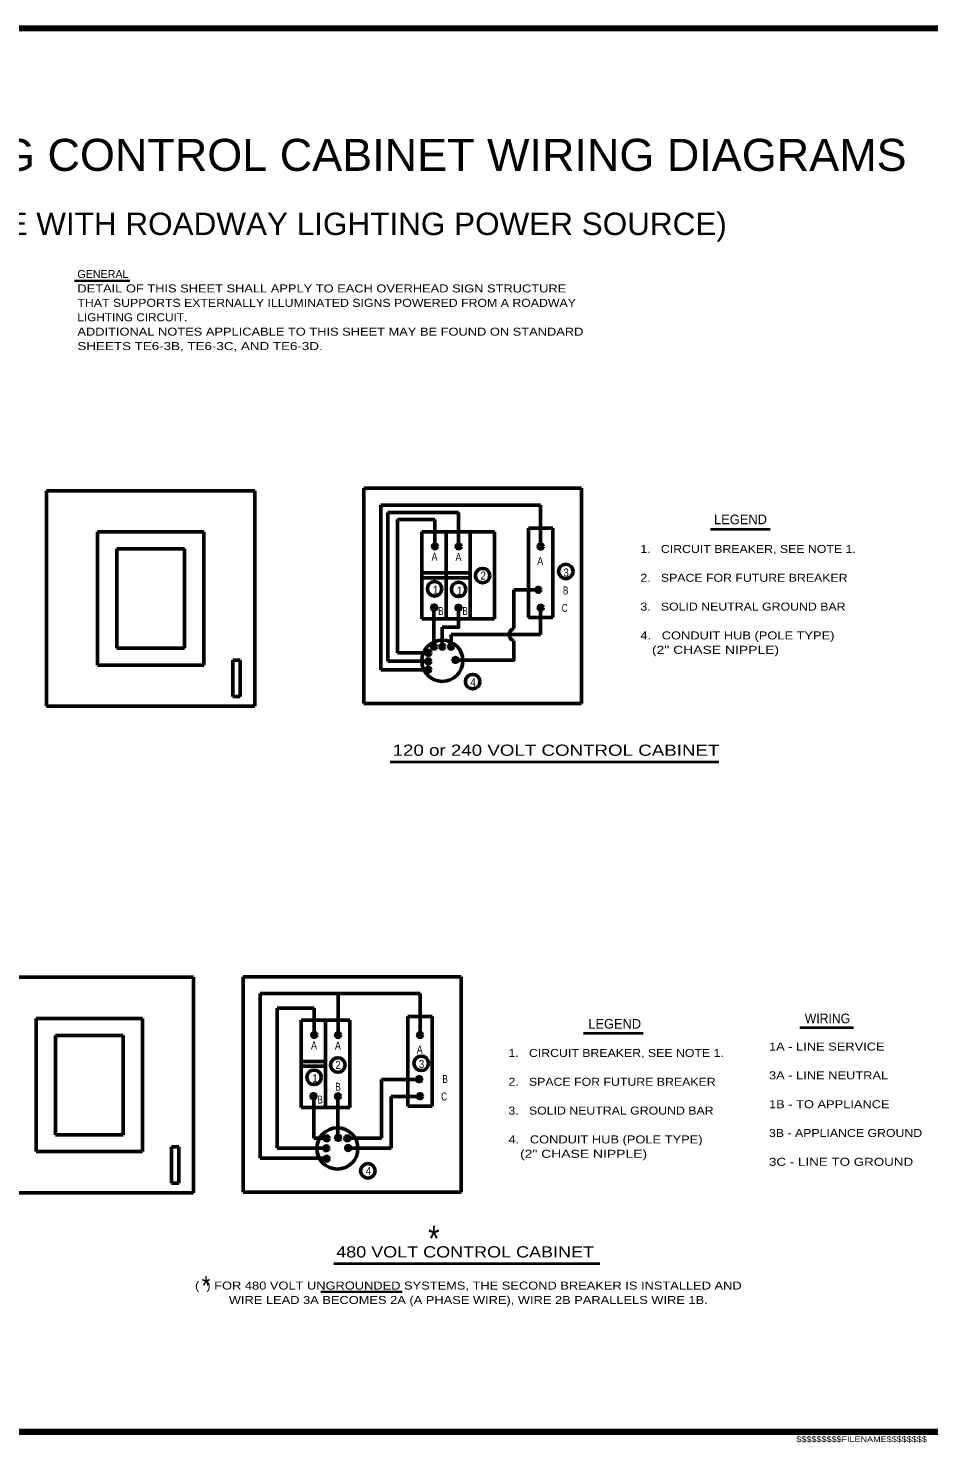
# Model space of a CAD drawing. Extents: x -38 to 818, y -13 to 531.
# Drawn here: x 250 to 588, y -6 to 524 of the extents above; entities that cross this region are included whole.
import ezdxf
from ezdxf.enums import TextEntityAlignment as Align

# ---------------------------------------------------------------- set-up
doc = ezdxf.new("R2010")
doc.units = 0
doc.header["$LTSCALE"] = 1.2
doc.layers.add('1', color=7, linetype='Continuous', lineweight=53)

msp = doc.modelspace()

# ---------------------------------------------------------------- hatches: boundary and pattern name
at = {"layer": '1'}
for points in [[(403.606, 330.209, 1), (401.791, 330.209, 1)], [(412.484, 330.191, 1), (410.669, 330.191, 1)], [(443.214, 330.181, 1), (441.399, 330.181, 1)], [(442.359, 313.935, 1), (440.544, 313.935, 1)], [(403.298, 307.273, 1), (401.483, 307.273, 1)], [(412.44, 307.195, 1), (410.625, 307.195, 1)], [(443.228, 307.234, 1), (441.413, 307.234, 1)], [(403.253, 292.596, 1), (401.438, 292.596, 1)], [(406.36, 292.596, 1), (404.545, 292.596, 1)], [(409.66, 292.596, 1), (407.845, 292.596, 1)], [(401.109, 290.282, 1), (399.294, 290.282, 1)], [(401.133, 287.126, 1), (399.318, 287.126, 1)], [(411.322, 287.656, 1), (409.507, 287.656, 1)], [(401.109, 283.994, 1), (399.294, 283.994, 1)], [(358.418, 147.099, 1), (356.603, 147.099, 1)], [(367.296, 147.081, 1), (365.481, 147.081, 1)], [(398.026, 147.072, 1), (396.211, 147.072, 1)], [(397.682, 130.519, 1), (395.867, 130.519, 1)], [(358.111, 124.163, 1), (356.296, 124.163, 1)], [(367.253, 124.085, 1), (365.438, 124.085, 1)], [(398.04, 124.124, 1), (396.225, 124.124, 1)], [(363.019, 108.354, 1), (361.204, 108.354, 1)], [(367.338, 108.551, 1), (365.523, 108.551, 1)], [(370.773, 108.354, 1), (368.958, 108.354, 1)], [(362.92, 104.623, 1), (361.105, 104.623, 1)], [(363.019, 100.695, 1), (361.204, 100.695, 1)], [(371.068, 104.721, 1), (369.253, 104.721, 1)]]:
    msp.add_hatch(color=256, dxfattribs=at).paths.add_polyline_path(points)

# ---------------------------------------------------------------- linework, layer by layer
at = {"layer": '1', "lineweight": 35}
for p, q in [((267.611, 429.766), (288.324, 429.766)), ((359.986, 50.809), (390.466, 50.809))]:
    msp.add_line(p, q, dxfattribs=at)
at = {"layer": '1'}
for p, q in [((257.116, 351.08), (257.116, 270.312)), ((257.116, 351.08), (335.161, 351.08)), ((335.161, 351.08), (335.161, 270.312)), ((376.022, 352.025), (376.022, 271.257)), ((376.022, 352.025), (457.697, 352.025)), ((457.697, 352.025), (457.697, 271.257)), ((382.375, 345.672), (382.375, 283.962)), ((382.375, 345.672), (442.309, 345.672)), ((442.309, 345.672), (442.309, 329.337)), ((385.097, 342.95), (385.097, 287.154)), ((385.097, 342.95), (411.559, 342.95)), ((388.727, 340.227), (388.727, 290.315)), ((388.727, 340.227), (402.66, 340.227)), ((402.66, 340.227), (402.66, 329.337)), ((411.559, 342.95), (411.559, 329.337)), ((276.173, 335.652), (276.173, 285.74)), ((276.173, 335.652), (316.103, 335.652)), ((316.103, 335.652), (316.103, 285.74)), ((397.802, 335.69), (397.802, 303.02)), ((397.802, 335.69), (425.027, 335.69)), ((406.877, 335.69), (406.877, 303.02)), ((415.952, 335.69), (415.952, 303.02)), ((425.027, 335.69), (425.027, 303.02)), ((437.772, 303.501), (437.772, 337.078)), ((437.772, 337.078), (446.847, 337.078)), ((446.847, 303.501), (446.847, 337.078)), ((283.434, 329.3), (283.434, 292.092)), ((283.434, 329.3), (308.844, 329.3)), ((308.844, 329.3), (308.844, 292.092)), ((397.802, 320.262), (415.952, 320.262)), ((415.952, 318.447), (397.802, 318.447)), ((432.287, 299.39), (432.287, 313.91)), ((432.287, 313.91), (442.309, 313.91)), ((402.334, 308.038), (402.334, 291.703)), ((442.309, 297.148), (442.309, 308.038)), ((425.027, 303.02), (397.802, 303.02)), ((437.772, 303.501), (446.847, 303.501)), ((405.453, 299.871), (405.453, 291.703)), ((408.732, 297.148), (442.309, 297.148)), ((408.732, 297.148), (408.732, 291.703)), ((283.434, 292.092), (308.844, 292.092)), ((326.994, 287.555), (326.994, 273.942)), ((326.994, 287.555), (329.716, 287.555)), ((329.716, 287.555), (329.716, 273.942)), ((385.097, 287.154), (401.095, 287.154)), ((388.727, 290.315), (401.095, 290.315)), ((276.173, 285.74), (316.103, 285.74)), ((382.375, 283.962), (401.095, 283.962)), ((326.994, 273.942), (329.716, 273.942)), ((376.022, 271.257), (457.697, 271.257)), ((257.116, 270.312), (335.161, 270.312)), ((234.134, 168.699), (312.179, 168.699)), ((312.179, 168.699), (312.179, 87.931)), ((330.835, 168.915), (330.835, 88.147)), ((330.835, 168.915), (412.51, 168.915)), ((412.51, 168.915), (412.51, 88.147)), ((337.187, 162.562), (337.187, 100.852)), ((337.187, 162.562), (397.122, 162.562)), ((366.372, 162.562), (366.372, 146.227)), ((397.122, 162.562), (397.122, 146.227)), ((343.54, 157.117), (343.54, 104.653)), ((343.54, 157.117), (357.473, 157.117)), ((357.473, 157.117), (357.473, 146.227)), ((392.585, 120.391), (392.585, 153.968)), ((392.585, 153.968), (401.66, 153.968)), ((401.66, 120.391), (401.66, 153.968)), ((253.191, 153.271), (253.191, 103.359)), ((253.191, 153.271), (293.121, 153.271)), ((293.121, 153.271), (293.121, 103.359)), ((352.615, 152.58), (352.615, 119.91)), ((352.615, 152.58), (370.765, 152.58)), ((361.69, 152.58), (361.69, 119.91)), ((370.765, 152.58), (370.765, 119.91)), ((260.451, 146.919), (260.451, 109.711)), ((260.451, 146.919), (285.861, 146.919)), ((285.861, 146.919), (285.861, 109.711)), ((352.615, 137.152), (361.69, 137.152)), ((361.69, 135.337), (352.615, 135.337)), ((396.771, 130.343), (382.637, 130.343)), ((382.637, 108.447), (382.637, 130.343)), ((357.312, 124.059), (357.312, 108.447)), ((366.342, 123.961), (366.342, 108.463)), ((397.262, 124.059), (386.267, 124.059)), ((386.267, 104.653), (386.267, 124.059)), ((370.765, 119.91), (352.615, 119.91)), ((392.585, 120.391), (401.66, 120.391)), ((260.451, 109.711), (285.861, 109.711)), ((357.312, 108.447), (361.631, 108.447)), ((369.974, 108.447), (382.637, 108.447)), ((253.191, 103.359), (293.121, 103.359)), ((304.011, 105.174), (304.011, 91.561)), ((304.011, 105.174), (306.734, 105.174)), ((306.734, 105.174), (306.734, 91.561)), ((337.187, 100.852), (361.631, 100.852)), ((343.54, 104.653), (361.631, 104.653)), ((369.974, 104.653), (386.267, 104.653)), ((304.011, 91.561), (306.734, 91.561)), ((234.134, 87.931), (312.179, 87.931)), ((330.835, 88.147), (412.51, 88.147))]:
    msp.add_line(p, q, dxfattribs=at)
at = {"layer": '1', "lineweight": 40}
for p, q in [((505.993, 336.634), (528.324, 336.634)), ((385.936, 249.442), (509.163, 249.442)), ((539.447, 149.877), (559.574, 149.877)), ((458.415, 147.739), (480.746, 147.739)), ((364.808, 61.42), (464.568, 61.42))]:
    msp.add_line(p, q, dxfattribs=at)
at = {"layer": '1', "lineweight": 158}
msp.add_line((811.159, -1.718), (19.559, -1.718), dxfattribs=at)
msp.add_lwpolyline([(811.159, 524.382), (19.459, 524.282), (19.559, -1.718)], dxfattribs=at)
at = {"layer": '1'}
for points in [[(405.453, 299.871), (411.572, 299.871), (411.572, 308.038)], [(409.6, 287.592), (432.287, 287.592), (432.287, 294.852)]]:
    msp.add_lwpolyline(points, dxfattribs=at)
for centre, radius in [((402.698, 330.209), 0.907), ((411.576, 330.191), 0.907), ((442.306, 330.181), 0.907), ((451.762, 320.804), 2.723), ((420.57, 319.244), 2.723), ((402.574, 314.323), 2.723), ((411.572, 314.083), 2.723), ((441.452, 313.935), 0.907), ((402.391, 307.273), 0.907), ((411.533, 307.195), 0.907), ((442.32, 307.234), 0.907), ((405.453, 287.321), 7.714), ((402.345, 292.596), 0.907), ((405.453, 292.596), 0.907), ((408.753, 292.596), 0.907), ((400.202, 290.282), 0.907), ((400.226, 287.126), 0.907), ((410.415, 287.656), 0.907), ((400.202, 283.994), 0.907), ((416.851, 279.52), 2.723), ((357.511, 147.099), 0.907), ((366.389, 147.081), 0.907), ((397.119, 147.072), 0.907), ((366.307, 135.828), 2.723), ((397.557, 136.455), 2.723), ((357.387, 131.213), 2.723), ((396.774, 130.519), 0.907), ((357.203, 124.163), 0.907), ((366.345, 124.085), 0.907), ((397.133, 124.124), 0.907), ((366.13, 104.532), 7.714), ((362.111, 108.354), 0.907), ((366.43, 108.551), 0.907), ((369.866, 108.354), 0.907), ((362.013, 104.623), 0.907), ((362.111, 100.695), 0.907), ((370.16, 104.721), 0.907), ((377.581, 96.15), 2.723)]:
    msp.add_circle(centre, radius, dxfattribs=at)
msp.add_arc((432.849, 297.121), 2.337, 103.91543, 256.08457, dxfattribs=at)

# ---------------------------------------------------------------- texts
for s, height, width, p in [('SIGN LIGHTING CONTROL CABINET WIRING DIAGRAMS', 12, 1.05, (127.345, 470.943)), ('(FOR USE WITH ROADWAY LIGHTING POWER SOURCE)', 8.4, 1.05, (193.641, 446.894)), ('DETAIL OF THIS SHEET SHALL APPLY TO EACH OVERHEAD SIGN STRUCTURE', 3, 1.2, (268.68, 425.376)), ('THAT SUPPORTS EXTERNALLY ILLUMINATED SIGNS POWERED FROM A ROADWAY', 3, 1.15, (268.68, 419.976)), ('LIGHTING CIRCUIT.', 3, 1.1, (268.68, 414.576)), ('ADDITIONAL NOTES APPLICABLE TO THIS SHEET MAY BE FOUND ON STANDARD', 3, 1.2, (268.68, 409.176)), ('SHEETS TE6-3B, TE6-3C, AND TE6-3D.', 3, 1.25, (268.68, 403.776)), ('1.   CIRCUIT BREAKER, SEE NOTE 1.', 3, 1.15, (479.695, 327.728)), ('A', 3, 0.85, (401.414, 324.789)), ('A', 3, 0.85, (410.38, 324.713)), ('A', 3, 0.85, (441.045, 323.203)), ('2', 3, 0.9, (419.783, 317.77)), ('3', 3, 0.9, (450.888, 318.911)), ('2.   SPACE FOR FUTURE BREAKER', 3, 1.15, (479.695, 316.929)), ('B', 3, 0.75, (450.706, 312.185)), ('B', 3, 0.75, (403.886, 304.484)), ('B', 3, 0.75, (413.01, 304.484)), ('C', 3, 0.75, (450.252, 305.653)), ('3.   SOLID NEUTRAL GROUND BAR', 3, 1.15, (479.695, 306.129)), ('4.   CONDUIT HUB (POLE TYPE)', 3, 1.2, (479.695, 295.329)), ('   (2" CHASE NIPPLE)', 3, 1.3, (479.695, 289.929)), ('4', 3, 0.95, (415.913, 277.76)), ('120 or 240 VOLT CONTROL CABINET', 4.2, 1.25, (386.825, 251.709)), ('WIRING', 3.6, 0.95, (541.326, 151.488)), ('A', 3, 0.85, (356.227, 141.68)), ('A', 3, 0.85, (365.192, 141.603)), ('1A - LINE SERVICE', 3, 1.2, (527.908, 141.24)), ('A', 3, 0.85, (395.857, 140.093)), ('1.   CIRCUIT BREAKER, SEE NOTE 1.', 3, 1.15, (430.243, 138.833)), ('2', 3, 0.9, (365.374, 134.344)), ('3', 3, 0.9, (396.667, 134.687)), ('3A - LINE NEUTRAL', 3, 1.2, (527.908, 130.44)), ('B', 3, 0.75, (365.376, 126.168)), ('B', 3, 0.75, (405.519, 129.075)), ('2.   SPACE FOR FUTURE BREAKER', 3, 1.15, (430.243, 128.033)), ('B', 3, 0.75, (358.699, 121.374)), ('C', 3, 0.75, (405.065, 122.543)), ('1B - TO APPLIANCE', 3, 1.2, (527.908, 119.64)), ('3.   SOLID NEUTRAL GROUND BAR', 3, 1.15, (430.243, 117.233)), ('3B - APPLIANCE GROUND', 3, 1.15, (527.908, 108.84)), ('4.   CONDUIT HUB (POLE TYPE)', 3, 1.2, (430.243, 106.433)), ('   (2" CHASE NIPPLE)', 3, 1.3, (430.243, 101.033)), ('3C - LINE TO GROUND', 3, 1.25, (527.908, 98.04)), ('4', 3, 0.95, (376.758, 94.651)), ('*', 9.6, 0.85, (400.176, 65.966)), ('480 VOLT CONTROL CABINET', 4.2, 1.2, (365.697, 63.687)), ('*', 7.2, 0.85, (315.251, 49.495)), ('$$$$$$$$$FILENAME$$$$$$$$', 2.2, 1.15, (538.159, -5.518))]:
    msp.add_text(s, height=height, dxfattribs=dict(at, width=width)).set_placement(p)
for s, height, p in [('GENERAL', 3, (268.68, 430.776)), ('LEGEND', 3.6, (507.335, 338.513)), ('1', 3, (401.859, 312.427)), ('1', 3, (410.87, 312.089)), ('LEGEND', 3.6, (460.189, 149.474)), ('1', 3, (356.671, 129.317))]:
    msp.add_text(s, height=height, dxfattribs=at).set_placement(p)
at = {"layer": '1', "width": 1.2}
for s, p in [('(  ) FOR 480 VOLT UNGROUNDED SYSTEMS, THE SECOND BREAKER IS INSTALLED AND', (415.201, 51.659)), ('WIRE LEAD 3A BECOMES 2A (A PHASE WIRE), WIRE 2B PARALLELS WIRE 1B.', (415.201, 46.259))]:
    msp.add_text(s, height=3, dxfattribs=at).set_placement(p, align=Align.CENTER)

doc.saveas('drawing.dxf')
